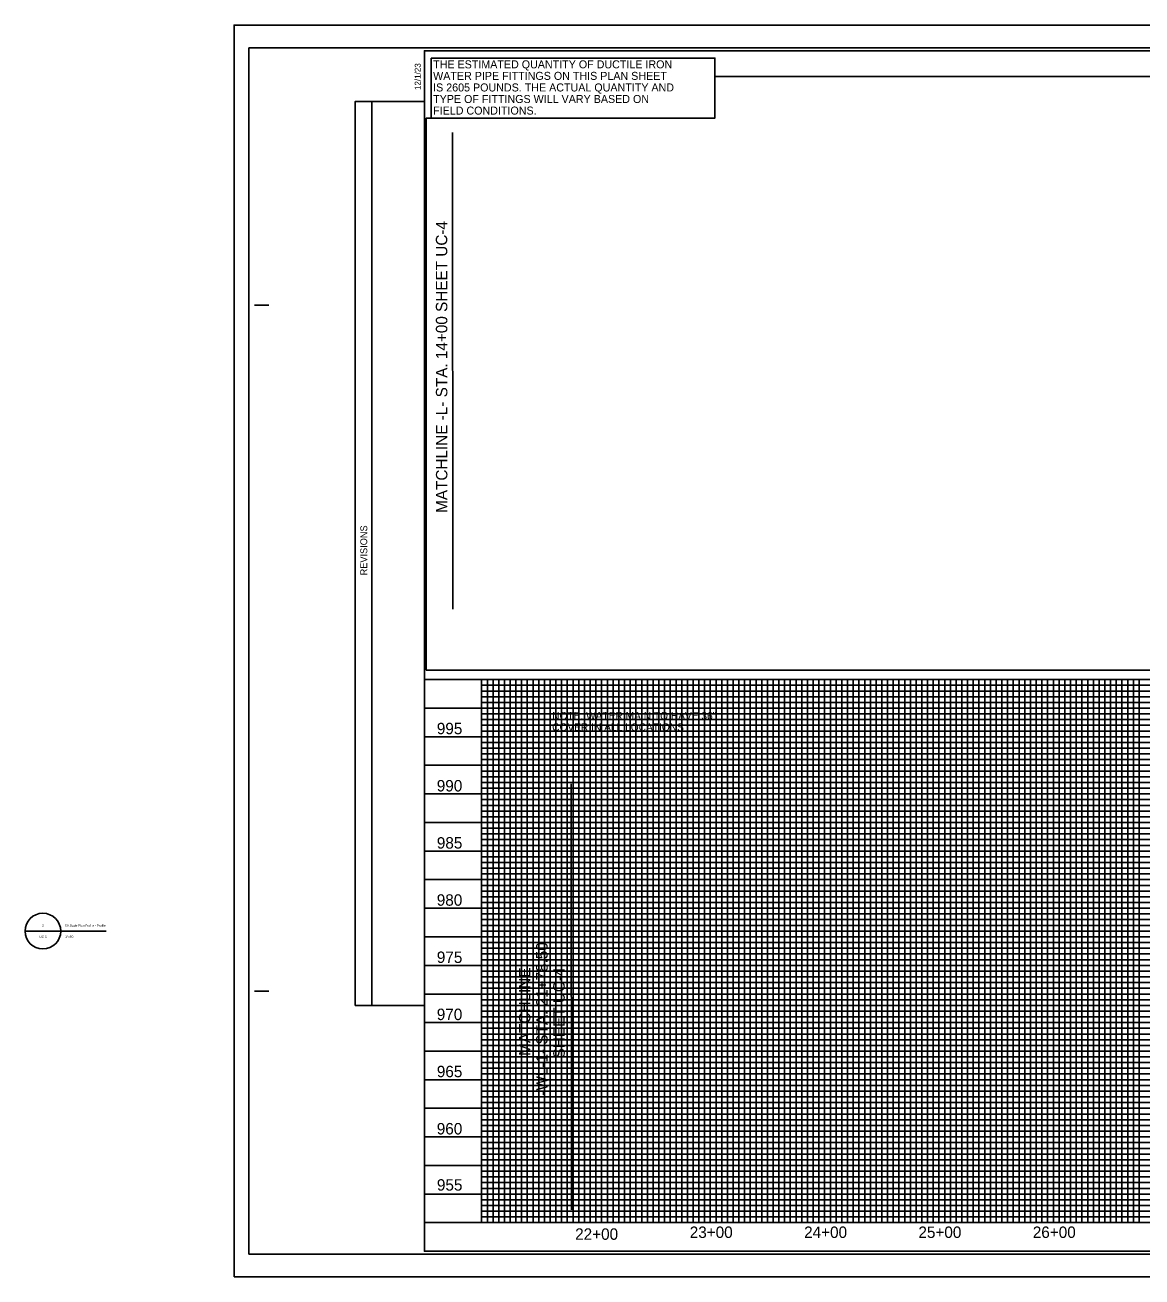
# Model space of a CAD drawing. Extents: x 0 to 2694, y -1 to 1501.
# Drawn here: x -0.277 to 1.351, y 0.008 to 1.833 of the extents above; entities that cross this region are included whole.
import ezdxf

# ---------------------------------------------------------------- set-up
doc = ezdxf.new("R2010")
doc.units = 0
for name, color, linetype in [('11 x 17 Ledger Page CELL', 7, 'Continuous'), ('Aband Utility MH (B1) CELL', 7, 'Continuous'), ('Aband Utility MH (St) CELL', 7, 'Continuous'), ('Air Release (M1) CELL', 7, 'Continuous'), ('COGO Default Point Elevation', 7, 'Continuous'), ('Concrete Pattern CELL', 7, 'Continuous'), ('Exist Utilities Sanitary Sewer Clean-Out CELL', 7, 'Continuous'), ('P_UTL_Water', 7, 'Continuous')]:
    doc.layers.add(name, color=color, linetype=linetype)

msp = doc.modelspace()

# ---------------------------------------------------------------- linework, layer by layer
at = {"layer": '11 x 17 Ledger Page CELL'}
for p, q in [((0.305, 0.8375), (2.5967, 0.8375)), ((2.805, 0.7542), (0.305, 0.7542)), ((0.305, 0.7542), (0.305, 0.6708)), ((0.305, 0.6708), (2.805, 0.6708)), ((2.805, 0.5875), (0.305, 0.5875)), ((0.305, 0.5875), (0.305, 0.5042)), ((0.305, 0.5042), (2.805, 0.5042)), ((2.805, 0.4208), (0.305, 0.4208)), ((0.305, 0.4208), (0.305, 0.3375)), ((0.305, 0.3375), (2.805, 0.3375)), ((2.805, 0.2542), (0.305, 0.2542)), ((0.305, 0.2542), (0.305, 0.1708)), ((0.305, 0.1708), (2.805, 0.1708))]:
    msp.add_line(p, q, dxfattribs=at)
for points in [[(0.43, 0.0875), (0.43, 0.8792), (0.5133, 0.8792), (0.5133, 0.0875)], [(0.5967, 0.0875), (0.5967, 0.8792), (0.68, 0.8792), (0.68, 0.0875)], [(0.7633, 0.0875), (0.7633, 0.8792), (0.8467, 0.8792), (0.8467, 0.0875)], [(0.93, 0.0875), (0.93, 0.8792), (1.0133, 0.8792), (1.0133, 0.0875)], [(1.0967, 0.0875), (1.0967, 0.8792), (1.18, 0.8792), (1.18, 0.0875)], [(1.2633, 0.0875), (1.2633, 0.8792), (1.3467, 0.8792), (1.3467, 0.0875)]]:
    msp.add_lwpolyline(points, dxfattribs=at)
at = {"layer": 'Aband Utility MH (B1) CELL'}
for p, q in [((-0.2771, 0.5125), (-0.225, 0.5125)), ((-0.2771, 0.5125), (-0.225, 0.5125)), ((-0.2771, 0.5125), (-0.225, 0.5125)), ((-0.2508, 0.5125), (-0.1587, 0.5125)), ((-0.2508, 0.5125), (-0.1587, 0.5125)), ((-0.2508, 0.5125), (-0.1587, 0.5125))]:
    msp.add_line(p, q, dxfattribs=at)
msp.add_circle((-0.2511, 0.5125), 0.026, dxfattribs=at)
msp.add_circle((-0.2511, 0.5125), 0.026, dxfattribs=at)
msp.add_circle((-0.2511, 0.5125), 0.026, dxfattribs=at)
at = {"layer": 'Aband Utility MH (St) CELL'}
msp.add_lwpolyline([(0.315, 1.7851), (0.7284, 1.7851), (0.7284, 1.6977), (0.315, 1.6977)], close=True, dxfattribs=at)
at = {"layer": 'Air Release (M1) CELL'}
msp.add_lwpolyline([(0.3075, 0.8929), (0.3076, 1.6978), (0.7284, 1.6977), (0.7284, 1.7582), (2.4697, 1.7582), (2.4697, 1.5021), (2.7791, 1.5021), (2.7809, 1.0475), (2.2746, 1.0478), (2.2735, 0.8929)], close=True, dxfattribs=at)
at = {"layer": 'COGO Default Point Elevation'}
for p, q in [((0.2283, 0.4042), (0.2283, 1.7219)), ((0.3461, 1.6767), (0.3464, 0.9819)), ((0.0575, 1.425), (0.0783, 1.425)), ((0.5189, 0.7271), (0.5192, 0.1061)), ((0.0575, 0.425), (0.0783, 0.425)), ((2.805, 0.0875), (0.305, 0.0875)), ((0.305, 0.0458), (0.305, 0.0458)), ((0.305, 0.0458), (0.305, 0.0458)), ((0.305, 0.0458), (0.305, 0.0458)), ((0.305, 0.0458), (0.305, 0.0458)), ((0.305, 0.0458), (0.305, 0.0458))]:
    msp.add_line(p, q, dxfattribs=at)
for points in [[(0.0275, 0.0083), (2.8333, 0.0083), (2.8333, 1.8333), (0.0275, 1.8333)], [(0.0492, 0.0417), (2.8258, 0.0417), (2.8258, 1.8), (0.0492, 1.8)], [(2.805, 1.7958), (0.305, 1.7958), (0.305, 0.0458), (2.805, 0.0458)], [(0.2041, 0.4042), (0.2041, 1.7219), (0.305, 1.7219), (0.305, 0.4042)], [(0.3883, 0.8792), (2.5967, 0.8792), (2.5967, 0.7958), (2.7217, 0.7958), (2.7217, 0.0875), (0.3883, 0.0875)]]:
    msp.add_lwpolyline(points, close=True, dxfattribs=at)
at = {"layer": 'Exist Utilities Sanitary Sewer Clean-Out CELL'}
for points in [[(0.3967, 0.0875), (0.3967, 0.8792), (0.405, 0.8792), (0.405, 0.0875)], [(0.4133, 0.0875), (0.4133, 0.8792), (0.4217, 0.8792), (0.4217, 0.0875)], [(0.4383, 0.0875), (0.4383, 0.8792), (0.4467, 0.8792), (0.4467, 0.0875)], [(0.455, 0.0875), (0.455, 0.8792), (0.4633, 0.8792), (0.4633, 0.0875)], [(0.48, 0.0875), (0.48, 0.8792), (0.4883, 0.8792), (0.4883, 0.0875)], [(0.4967, 0.0875), (0.4967, 0.8792), (0.505, 0.8792), (0.505, 0.0875)], [(0.5217, 0.0875), (0.5217, 0.8792), (0.53, 0.8792), (0.53, 0.0875)], [(0.5383, 0.0875), (0.5383, 0.8792), (0.5467, 0.8792), (0.5467, 0.0875)], [(0.5633, 0.0875), (0.5633, 0.8792), (0.5717, 0.8792), (0.5717, 0.0875)], [(0.58, 0.0875), (0.58, 0.8792), (0.5883, 0.8792), (0.5883, 0.0875)], [(0.605, 0.0875), (0.605, 0.8792), (0.6133, 0.8792), (0.6133, 0.0875)], [(0.6217, 0.0875), (0.6217, 0.8792), (0.63, 0.8792), (0.63, 0.0875)], [(0.6467, 0.0875), (0.6467, 0.8792), (0.655, 0.8792), (0.655, 0.0875)], [(0.6633, 0.0875), (0.6633, 0.8792), (0.6717, 0.8792), (0.6717, 0.0875)], [(0.6883, 0.0875), (0.6883, 0.8792), (0.6967, 0.8792), (0.6967, 0.0875)], [(0.705, 0.0875), (0.705, 0.8792), (0.7133, 0.8792), (0.7133, 0.0875)], [(0.73, 0.0875), (0.73, 0.8792), (0.7383, 0.8792), (0.7383, 0.0875)], [(0.7467, 0.0875), (0.7467, 0.8792), (0.755, 0.8792), (0.755, 0.0875)], [(0.7717, 0.0875), (0.7717, 0.8792), (0.78, 0.8792), (0.78, 0.0875)], [(0.7883, 0.0875), (0.7883, 0.8792), (0.7967, 0.8792), (0.7967, 0.0875)], [(0.8133, 0.0875), (0.8133, 0.8792), (0.8217, 0.8792), (0.8217, 0.0875)], [(0.83, 0.0875), (0.83, 0.8792), (0.8383, 0.8792), (0.8383, 0.0875)], [(0.855, 0.0875), (0.855, 0.8792), (0.8633, 0.8792), (0.8633, 0.0875)], [(0.8717, 0.0875), (0.8717, 0.8792), (0.88, 0.8792), (0.88, 0.0875)], [(0.8967, 0.0875), (0.8967, 0.8792), (0.905, 0.8792), (0.905, 0.0875)], [(0.9133, 0.0875), (0.9133, 0.8792), (0.9217, 0.8792), (0.9217, 0.0875)], [(0.9383, 0.0875), (0.9383, 0.8792), (0.9467, 0.8792), (0.9467, 0.0875)], [(0.955, 0.0875), (0.955, 0.8792), (0.9633, 0.8792), (0.9633, 0.0875)], [(0.98, 0.0875), (0.98, 0.8792), (0.9883, 0.8792), (0.9883, 0.0875)], [(0.9967, 0.0875), (0.9967, 0.8792), (1.005, 0.8792), (1.005, 0.0875)], [(1.0217, 0.0875), (1.0217, 0.8792), (1.03, 0.8792), (1.03, 0.0875)], [(1.0383, 0.0875), (1.0383, 0.8792), (1.0467, 0.8792), (1.0467, 0.0875)], [(1.0633, 0.0875), (1.0633, 0.8792), (1.0717, 0.8792), (1.0717, 0.0875)], [(1.08, 0.0875), (1.08, 0.8792), (1.0883, 0.8792), (1.0883, 0.0875)], [(1.105, 0.0875), (1.105, 0.8792), (1.1133, 0.8792), (1.1133, 0.0875)], [(1.1217, 0.0875), (1.1217, 0.8792), (1.13, 0.8792), (1.13, 0.0875)], [(1.1467, 0.0875), (1.1467, 0.8792), (1.155, 0.8792), (1.155, 0.0875)], [(1.1633, 0.0875), (1.1633, 0.8792), (1.1717, 0.8792), (1.1717, 0.0875)], [(1.1883, 0.0875), (1.1883, 0.8792), (1.1967, 0.8792), (1.1967, 0.0875)], [(1.205, 0.0875), (1.205, 0.8792), (1.2133, 0.8792), (1.2133, 0.0875)], [(1.23, 0.0875), (1.23, 0.8792), (1.2383, 0.8792), (1.2383, 0.0875)], [(1.2467, 0.0875), (1.2467, 0.8792), (1.255, 0.8792), (1.255, 0.0875)], [(1.2717, 0.0875), (1.2717, 0.8792), (1.28, 0.8792), (1.28, 0.0875)], [(1.2883, 0.0875), (1.2883, 0.8792), (1.2967, 0.8792), (1.2967, 0.0875)], [(1.3133, 0.0875), (1.3133, 0.8792), (1.3217, 0.8792), (1.3217, 0.0875)], [(1.33, 0.0875), (1.33, 0.8792), (1.3383, 0.8792), (1.3383, 0.0875)], [(2.5967, 0.8708), (0.3883, 0.8708)], [(2.5967, 0.8542), (0.3883, 0.8542), (0.3883, 0.8625), (2.5967, 0.8625)], [(2.5967, 0.8292), (0.3883, 0.8292), (0.3883, 0.8375), (0.3883, 0.8458), (2.5967, 0.8458)], [(2.5967, 0.8125), (0.3883, 0.8125), (0.3883, 0.8208), (2.5967, 0.8208)], [(2.7217, 0.7875), (0.3883, 0.7875), (0.3883, 0.7958), (0.3883, 0.8042), (2.5967, 0.8042)], [(2.7217, 0.7708), (0.3883, 0.7708), (0.3883, 0.7792), (2.7217, 0.7792)], [(2.7217, 0.7458), (0.3883, 0.7458), (0.3883, 0.7542), (0.3883, 0.7625), (2.7217, 0.7625)], [(2.7217, 0.7292), (0.3883, 0.7292), (0.3883, 0.7375), (2.7217, 0.7375)], [(0.3883, 0.7042), (0.3883, 0.7125), (0.3883, 0.7208), (2.7217, 0.7208)], [(2.7217, 0.6958), (0.3883, 0.6958), (0.3883, 0.7042), (2.7217, 0.7042)], [(2.7217, 0.6792), (0.3883, 0.6792), (0.3883, 0.6875), (2.7217, 0.6875)], [(2.7217, 0.6542), (0.3883, 0.6542), (0.3883, 0.6625), (2.7217, 0.6625)], [(2.7217, 0.6375), (0.3883, 0.6375), (0.3883, 0.6458), (2.7217, 0.6458)], [(2.7217, 0.6125), (0.3883, 0.6125), (0.3883, 0.6208), (2.7217, 0.6208)], [(2.7217, 0.5958), (0.3883, 0.5958), (0.3883, 0.6042), (2.7217, 0.6042)], [(2.7217, 0.5708), (0.3883, 0.5708), (0.3883, 0.5792), (2.7217, 0.5792)], [(2.7217, 0.5542), (0.3883, 0.5542), (0.3883, 0.5625), (2.7217, 0.5625)], [(2.7217, 0.5292), (0.3883, 0.5292), (0.3883, 0.5375), (2.7217, 0.5375)], [(2.7217, 0.5125), (0.3883, 0.5125), (0.3883, 0.5208), (2.7217, 0.5208)], [(2.7217, 0.4875), (0.3883, 0.4875), (0.3883, 0.4958), (2.7217, 0.4958)], [(2.7217, 0.4708), (0.3883, 0.4708), (0.3883, 0.4792), (2.7217, 0.4792)], [(2.7217, 0.4458), (0.3883, 0.4458), (0.3883, 0.4542), (2.7217, 0.4542)], [(2.7217, 0.4292), (0.3883, 0.4292), (0.3883, 0.4375), (2.7217, 0.4375)], [(2.7217, 0.4042), (0.3883, 0.4042), (0.3883, 0.4125), (2.7217, 0.4125)], [(2.7217, 0.3875), (0.3883, 0.3875), (0.3883, 0.3958), (2.7217, 0.3958)], [(2.7217, 0.3625), (0.3883, 0.3625), (0.3883, 0.3708), (2.7217, 0.3708)], [(2.7217, 0.3458), (0.3883, 0.3458), (0.3883, 0.3542), (2.7217, 0.3542)], [(2.7217, 0.3208), (0.3883, 0.3208), (0.3883, 0.3292), (2.7217, 0.3292)], [(2.7217, 0.3042), (0.3883, 0.3042), (0.3883, 0.3125), (2.7217, 0.3125)], [(2.7217, 0.2792), (0.3883, 0.2792), (0.3883, 0.2875), (2.7217, 0.2875)], [(2.7217, 0.2625), (0.3883, 0.2625), (0.3883, 0.2708), (2.7217, 0.2708)], [(2.7217, 0.2375), (0.3883, 0.2375), (0.3883, 0.2458), (2.7217, 0.2458)], [(2.7217, 0.2208), (0.3883, 0.2208), (0.3883, 0.2292), (2.7217, 0.2292)], [(0.3883, 0.1958), (0.3883, 0.2042), (2.7217, 0.2042)], [(0.3883, 0.0958), (2.7217, 0.0958), (2.7217, 0.1042), (0.3883, 0.1042), (0.3883, 0.1125), (2.7217, 0.1125), (2.7217, 0.1208), (0.3883, 0.1208), (0.3883, 0.1292), (0.3883, 0.1375), (2.7217, 0.1375), (2.7217, 0.1458), (0.3883, 0.1458), (0.3883, 0.1542), (2.7217, 0.1542), (2.7217, 0.1625), (0.3883, 0.1625), (0.3883, 0.1708), (0.3883, 0.1792), (2.7217, 0.1792), (2.7217, 0.1875), (0.3883, 0.1875), (0.3883, 0.1958), (2.7217, 0.1958)]]:
    msp.add_lwpolyline(points, dxfattribs=at)
at = {"layer": 'P_UTL_Water'}
for points in [[(0.305, 0.8792), (2.5967, 0.8792)], [(0.305, 0.8792), (0.305, 0.0875)], [(0.3883, 0.0875), (0.3883, 0.8792), (0.4717, 0.8792), (0.4717, 0.0875)], [(0.555, 0.0875), (0.555, 0.8792), (0.6383, 0.8792), (0.6383, 0.0875)], [(0.7217, 0.0875), (0.7217, 0.8792), (0.805, 0.8792), (0.805, 0.0875)], [(0.8883, 0.0875), (0.8883, 0.8792), (0.9717, 0.8792), (0.9717, 0.0875)], [(1.055, 0.0875), (1.055, 0.8792), (1.1383, 0.8792), (1.1383, 0.0875)], [(1.2217, 0.0875), (1.2217, 0.8792), (1.305, 0.8792), (1.305, 0.0875)], [(2.805, 0.7958), (0.305, 0.7958), (0.305, 0.7125), (2.805, 0.7125)], [(2.805, 0.6292), (0.305, 0.6292), (0.305, 0.5458), (2.805, 0.5458)], [(2.805, 0.4625), (0.305, 0.4625), (0.305, 0.3792), (2.805, 0.3792)], [(2.805, 0.2958), (0.305, 0.2958), (0.305, 0.2125), (2.805, 0.2125)], [(2.805, 0.1292), (0.305, 0.1292)]]:
    msp.add_lwpolyline(points, dxfattribs=at)

# ---------------------------------------------------------------- texts
at = {"layer": 'Aband Utility MH (B1) CELL'}
for s, height, p in [('2', 0.00328, (-0.2522, 0.519)), ('2', 0.00328, (-0.2522, 0.519)), ('2', 0.00328, (-0.2522, 0.519)), ('50 Scale Plan Profile - Profile', 0.003281, (-0.2185, 0.519)), ('50 Scale Plan Profile - Profile', 0.003281, (-0.2185, 0.519)), ('50 Scale Plan Profile - Profile', 0.003281, (-0.2185, 0.519)), ('UC-5', 0.00328, (-0.2561, 0.5026)), ('UC-5', 0.00328, (-0.2561, 0.5026)), ('UC-5', 0.00328, (-0.2561, 0.5026)), ('1"=50\'', 0.00328, (-0.2185, 0.5026)), ('1"=50\'', 0.00328, (-0.2185, 0.5026)), ('1"=50\'', 0.00328, (-0.2185, 0.5026))]:
    msp.add_text(s, height=height, dxfattribs=at).set_placement(p)
at = {"layer": 'Aband Utility MH (St) CELL'}
for s, p in [('THE ESTIMATED QUANTITY OF DUCTILE IRON', (0.3177, 1.7702)), ('WATER PIPE FITTINGS ON THIS PLAN SHEET', (0.3177, 1.7534)), ('IS 2605 POUNDS. THE ACTUAL QUANTITY AND', (0.3177, 1.7365)), ('TYPE OF FITTINGS WILL VARY BASED ON', (0.3177, 1.7197)), ('FIELD CONDITIONS.', (0.3177, 1.7028))]:
    msp.add_text(s, height=0.011667, dxfattribs=at).set_placement(p)
at = {"layer": 'COGO Default Point Elevation'}
for s, height, rotation, p in [('12/1/23', 0.00875, 90, (0.2996, 1.7386)), ('MATCHLINE -L- STA. 14+00 SHEET UC-4', 0.016667, 90.0236, (0.3385, 1.1222)), ('REVISIONS', 0.01, 90, (0.2216, 1.0311)), ('-WL-1- STA. 21+78.50 ', 0.016667, 90.0236, (0.4846, 0.2727)), ('MATCHLINE ', 0.01667, 90.0236, (0.4595, 0.3307)), ('SHEET UC-4', 0.01667, 90.0236, (0.5095, 0.3269))]:
    msp.add_text(s, height=height, rotation=rotation, dxfattribs=at).set_placement(p)
for s, p in [('995', (0.3231, 0.7995)), ('990', (0.323, 0.7161)), ('985', (0.3231, 0.6328)), ('980', (0.323, 0.5495)), ('975', (0.3231, 0.4661)), ('970', (0.323, 0.3828)), ('965', (0.3231, 0.2995)), ('960', (0.323, 0.2161)), ('955', (0.3232, 0.1342)), ('22+00', (0.5247, 0.0625)), ('23+00', (0.6917, 0.0652)), ('24+00', (0.8584, 0.0652)), ('25+00', (1.025, 0.0652)), ('26+00', (1.1917, 0.0652))]:
    msp.add_text(s, height=0.01667, dxfattribs=at).set_placement(p)
at = {"layer": 'Concrete Pattern CELL'}
for s, p in [('NOTE: WATER MAIN TO HAVE 36" ', (0.4912, 0.8209)), ('COVER IN ALL LOCATIONS', (0.4912, 0.8043))]:
    msp.add_text(s, height=0.011087, dxfattribs=at).set_placement(p)

doc.saveas('drawing.dxf')
